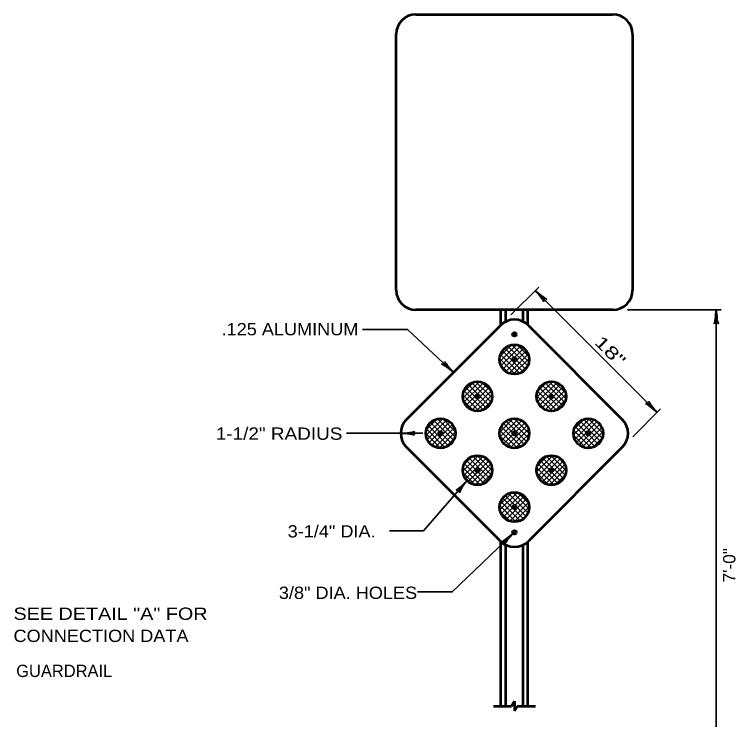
# Model space of a CAD drawing. Extents: x -54 to 626, y -41 to 399.
# Drawn here: x 179.4 to 325.9, y 49.1 to 192.4 of the extents above; entities that cross this region are included whole.
import ezdxf

# ---------------------------------------------------------------- set-up
doc = ezdxf.new("R2010")
doc.units = 0
doc.header["$LTSCALE"] = 0.9
doc.layers.add('1', color=7, linetype='Continuous', lineweight=35)

msp = doc.modelspace()

# ---------------------------------------------------------------- hatches: boundary and pattern name
at = {"layer": '1'}
for points in [[(281.3723, 127.3772, 1), (280.6223, 127.3772, 1)], [(281.3723, 122.2852, 1), (280.6223, 122.2852, 1)], [(273.8723, 114.7853, 1), (273.1223, 114.7853, 1)], [(288.8723, 114.7852, 1), (288.1223, 114.7852, 1)], [(266.3723, 107.2852, 1), (265.6223, 107.2852, 1)], [(281.3723, 107.2852, 1), (280.6223, 107.2852, 1)], [(296.3723, 107.2852, 1), (295.6223, 107.2852, 1)], [(273.8723, 99.7852, 1), (273.1223, 99.7852, 1)], [(288.8723, 99.7853, 1), (288.1223, 99.7853, 1)], [(281.3723, 92.2852, 1), (280.6223, 92.2852, 1)], [(281.3723, 87.1933, 1), (280.6223, 87.1933, 1)]]:
    msp.add_hatch(color=256, dxfattribs=at).paths.add_polyline_path(points)

# ---------------------------------------------------------------- linework, layer by layer
at = {"layer": '1', "lineweight": 53}
for p, q in [((260.9973, 192.3772), (300.9973, 192.3772)), ((256.9973, 136.3772), (256.9973, 188.3772)), ((304.9973, 188.3772), (304.9973, 136.3772)), ((300.9973, 132.3772), (260.9973, 132.3772)), ((278.2473, 129.284), (278.2473, 132.3772)), ((279.2473, 129.974), (279.2473, 132.3772)), ((282.7473, 129.9741), (282.7473, 132.3772)), ((283.7473, 129.284), (283.7473, 132.3772)), ((259.0769, 110.1137), (278.1688, 129.2056)), ((283.8257, 129.2056), (302.9176, 110.1137)), ((278.1688, 85.3649), (259.0769, 104.4568)), ((302.9176, 104.4568), (283.8257, 85.3649)), ((278.2473, 51.8772), (278.2473, 85.2865)), ((283.7473, 51.8772), (283.7473, 85.2865)), ((279.2473, 51.8772), (279.2473, 84.5965)), ((282.7473, 51.8772), (282.7473, 84.5965)), ((280.9973, 52.8772), (280.4199, 51.8772)), ((280.9973, 52.8772), (280.9973, 50.8772)), ((276.7473, 51.8772), (280.4199, 51.8772)), ((280.9973, 50.8772), (281.5746, 51.8772)), ((281.5746, 51.8772), (285.2473, 51.8772))]:
    msp.add_line(p, q, dxfattribs=at)
at = {"layer": '1'}
for p, q in [((280.2901, 131.3268), (285.947, 136.9837)), ((285.2398, 136.2766), (309.9885, 111.5278)), ((303.9973, 132.3772), (322.9973, 132.3772)), ((321.9973, 132.3772), (321.9973, 25.3772)), ((278.0329, 121.8588), (281.426, 125.252)), ((278.0842, 122.9707), (280.3137, 125.2003)), ((278.2742, 121.0395), (282.2457, 125.011)), ((278.6792, 120.3838), (282.896, 124.6007)), ((283.2723, 120.341), (279.0498, 124.5635)), ((283.6929, 120.981), (279.6937, 124.9803)), ((283.9497, 121.7848), (280.4976, 125.2371)), ((283.9344, 122.8609), (281.5714, 125.2239)), ((282.0212, 119.4708), (278.1833, 123.3087)), ((282.7171, 119.8356), (278.5449, 124.0078)), ((279.2254, 119.8694), (283.4107, 124.0547)), ((279.912, 119.4953), (283.7867, 123.37)), ((281.136, 119.2953), (278.0039, 122.4274)), ((280.7758, 119.2984), (283.9817, 122.5044)), ((279.8488, 119.5218), (278.2222, 121.1484)), ((282.0031, 119.4651), (283.8259, 121.2879)), ((270.5224, 114.4162), (273.8635, 117.7574)), ((270.6065, 115.561), (272.7289, 117.6834)), ((270.7516, 113.5848), (274.6968, 117.53)), ((276.2534, 113.619), (272.3268, 117.5457)), ((276.4728, 114.4603), (273.1689, 117.7642)), ((276.38, 115.6137), (274.3293, 117.6645)), ((285.5127, 114.5304), (288.7494, 117.7671)), ((285.6516, 115.7299), (287.5437, 117.6221)), ((285.7145, 113.6716), (289.6074, 117.5644)), ((291.2157, 113.5329), (287.2427, 117.5059)), ((291.4584, 114.3508), (288.0598, 117.7495)), ((291.4139, 115.456), (289.1683, 117.7015)), ((274.6647, 112.0258), (270.7403, 115.9501)), ((275.3357, 112.4154), (271.1322, 116.6188)), ((271.1486, 112.9212), (275.3576, 117.1301)), ((275.8627, 112.9491), (271.6608, 117.1508)), ((271.688, 112.3998), (275.8818, 116.5938)), ((272.3642, 112.0155), (276.2685, 115.9197)), ((289.5777, 111.9889), (285.7047, 115.8618)), ((290.2617, 112.3656), (286.0777, 116.5495)), ((286.0977, 112.9942), (290.2872, 117.1836)), ((290.8062, 112.8816), (286.5888, 117.0992)), ((286.6195, 112.4552), (290.8292, 116.6649)), ((287.277, 112.0521), (291.235, 116.0101)), ((273.8242, 111.8056), (270.5222, 115.1076)), ((273.215, 111.8055), (276.4773, 115.0679)), ((288.7087, 111.7972), (285.5107, 114.9952)), ((288.1039, 111.8183), (291.469, 115.1834)), ((272.6571, 111.912), (270.6222, 113.9469)), ((274.4033, 111.9333), (276.3522, 113.8821)), ((287.4775, 111.9677), (285.6846, 113.7607)), ((289.2213, 111.8751), (291.3998, 114.0537)), ((305.0387, 106.5781), (310.6957, 112.235)), ((263.0336, 106.855), (266.4303, 110.2516)), ((263.0827, 107.9647), (265.3194, 110.2014)), ((263.2758, 106.0364), (267.249, 110.0097)), ((268.6343, 105.8597), (264.5753, 109.9188)), ((268.9219, 106.6328), (265.3477, 110.2071)), ((268.9718, 107.6435), (266.3576, 110.2578)), ((278.0143, 107.5297), (280.7533, 110.2687)), ((278.0908, 106.5455), (281.732, 110.1868)), ((278.3983, 105.7924), (282.4867, 109.8809)), ((283.8335, 106.3152), (280.031, 110.1177)), ((283.9952, 107.2142), (280.9306, 110.2787)), ((283.7096, 108.5603), (282.2672, 110.0027)), ((293.016, 106.9504), (296.3262, 110.2605)), ((293.1197, 108.1147), (295.1724, 110.1674)), ((293.2379, 106.1117), (297.1675, 110.0412)), ((298.8372, 106.3285), (295.0437, 110.1221)), ((298.9957, 107.2308), (295.9468, 110.2796)), ((298.6896, 108.5975), (297.3038, 109.9832)), ((267.6095, 104.7632), (263.4737, 108.8991)), ((263.6814, 105.3814), (267.8986, 109.5987)), ((268.1905, 105.243), (263.9578, 109.4756)), ((264.2279, 104.8673), (268.4126, 109.052)), ((282.3508, 104.6158), (278.3248, 108.6418)), ((282.9819, 105.0454), (278.7538, 109.2735)), ((278.8579, 105.1913), (283.0908, 109.4243)), ((283.479, 105.609), (279.3218, 109.7662)), ((279.4506, 104.7234), (283.5617, 108.8344)), ((297.3623, 104.6214), (293.3311, 108.6527)), ((293.6319, 105.4449), (297.8345, 109.6476)), ((297.9909, 105.0535), (293.7613, 109.2831)), ((294.1655, 104.9179), (298.3646, 109.117)), ((298.4856, 105.6195), (294.3317, 109.7732)), ((294.8357, 104.5274), (298.7575, 108.4492)), ((257.9053, 107.2852), (246.9053, 107.2852)), ((257.9053, 107.2852), (262.3932, 107.287)), ((265.9607, 104.2908), (263.0037, 107.2477)), ((266.8848, 104.4273), (263.135, 108.1771)), ((264.9152, 104.4939), (268.7879, 108.3667)), ((265.7798, 104.2979), (268.982, 107.5001)), ((281.5605, 104.3455), (278.0547, 107.8513)), ((280.1909, 104.403), (283.8837, 108.0959)), ((281.1441, 104.2956), (283.9931, 107.1446)), ((296.5751, 104.348), (293.0581, 107.865)), ((295.6786, 104.3097), (298.9746, 107.6057)), ((264.4924, 104.6983), (263.3982, 105.7926)), ((267.0098, 104.4672), (268.8241, 106.2815)), ((280.517, 104.3283), (278.0434, 106.8019)), ((282.8016, 104.8924), (283.3848, 105.4757)), ((295.5363, 104.3261), (293.0396, 106.8229)), ((296.8438, 104.4142), (298.8678, 106.4382)), ((270.51, 99.5965), (273.686, 102.7726)), ((270.6972, 98.7231), (274.5577, 102.5836)), ((270.6981, 100.8452), (272.4374, 102.5847)), ((276.3313, 98.8075), (272.5238, 102.6151)), ((276.4948, 99.7047), (273.4213, 102.7782)), ((285.517, 99.4455), (288.8317, 102.7602)), ((285.6178, 100.6069), (287.6816, 102.6707)), ((285.74, 98.6078), (289.6718, 102.5397)), ((291.3174, 98.7649), (287.4819, 102.6004)), ((291.4933, 99.6497), (288.3677, 102.7752)), ((291.2594, 100.9442), (289.659, 102.5446)), ((274.8442, 97.1126), (270.8212, 101.1357)), ((271.0696, 98.0348), (275.2482, 102.2133)), ((275.4767, 97.5408), (271.2495, 101.7681)), ((271.5814, 97.486), (275.7999, 101.7045)), ((275.9753, 98.1029), (271.8162, 102.2621)), ((276.2211, 101.0392), (274.7513, 102.5088)), ((289.8061, 97.0942), (285.8007, 101.0997)), ((286.1344, 97.9416), (290.3379, 102.1451)), ((290.447, 97.514), (286.2246, 101.7363)), ((286.6688, 97.4153), (290.8672, 101.6137)), ((290.9537, 98.068), (286.7832, 102.2385)), ((274.0522, 96.8441), (270.5528, 100.3435)), ((272.2286, 97.0724), (276.212, 101.0559)), ((273.0422, 96.8254), (276.4597, 100.243)), ((289.0037, 96.836), (285.5416, 100.2981)), ((287.3399, 97.0258), (291.2592, 100.945)), ((288.184, 96.8092), (291.475, 100.1002)), ((273.0059, 96.8297), (270.5456, 99.29)), ((274.1357, 96.8582), (276.4264, 99.149)), ((287.9417, 96.8373), (285.5586, 99.2205)), ((289.3526, 96.9171), (291.3655, 98.93)), ((278.0358, 92.7443), (280.5364, 95.2448)), ((278.0607, 91.7084), (281.5752, 95.223)), ((283.9696, 91.9359), (280.6429, 95.2626)), ((278.3338, 90.9209), (282.363, 94.9502)), ((282.8193, 89.9042), (278.6201, 94.1034)), ((278.765, 90.2914), (282.995, 94.5214)), ((283.3501, 90.4341), (279.1448, 94.6393)), ((279.3299, 89.7957), (283.4863, 93.9522)), ((283.745, 91.0998), (279.8063, 95.0385)), ((283.8875, 93.0787), (281.7935, 95.1726)), ((281.3007, 89.3015), (278.0196, 92.5826)), ((282.1461, 89.5168), (278.2324, 93.4304)), ((280.038, 89.4432), (283.8347, 93.2399)), ((280.9459, 89.2903), (283.9935, 92.338)), ((280.1198, 89.4217), (278.1359, 91.4056)), ((282.3143, 89.5981), (283.6897, 90.9735))]:
    msp.add_line(p, q, dxfattribs=at)
for points in [[(268.6229, 119.6597), (259.2493, 128.3586), (250.1317, 128.3586)], [(271.3759, 97.6639), (262.5505, 87.4735), (255.6337, 87.4735)], [(280.7321, 86.9282), (268.3668, 75.0507), (261.2928, 75.0507)]]:
    msp.add_lwpolyline(points, dxfattribs=at)
at = {"layer": '1', "lineweight": 53}
for centre, radius in [((280.9973, 127.3772), 0.375), ((280.9973, 122.2852), 3), ((280.9973, 122.2852), 0.375), ((273.4973, 114.7853), 3), ((288.4973, 114.7852), 3), ((273.4973, 114.7853), 0.375), ((288.4973, 114.7852), 0.375), ((265.9973, 107.2852), 3), ((280.9973, 107.2852), 3), ((295.9973, 107.2852), 3), ((265.9973, 107.2852), 0.375), ((280.9973, 107.2852), 0.375), ((295.9973, 107.2852), 0.375), ((273.4973, 99.7852), 3), ((288.4973, 99.7853), 3), ((273.4973, 99.7852), 0.375), ((288.4973, 99.7853), 0.375), ((280.9973, 92.2852), 3), ((280.9973, 92.2852), 0.375), ((280.9973, 87.1933), 0.375)]:
    msp.add_circle(centre, radius, dxfattribs=at)
for centre, start, end in [((260.9973, 188.3772), 90, 180), ((300.9973, 188.3772), 0, 90), ((260.9973, 136.3772), 180, 270), ((300.9973, 136.3772), 270, 0), ((280.9973, 126.3772), 45.00033, 135), ((261.9054, 107.2852), 135, 225), ((300.0892, 107.2853), 315, 44.99948), ((280.9973, 88.1934), 225, 315)]:
    msp.add_arc(centre, 4, start, end, dxfattribs=at)
at = {"layer": '1', "lineweight": 40}
for centre, major_axis, ratio, start_param, end_param in [((285.8825, 135.3346), (-1.1178, 1.3662), 0.07063, 3.14071475, 5.41810995), ((285.8825, 135.3346), (-1.1178, 1.3662), 0.07063, 3.14071475, 5.41810995), ((286.2068, 135.7004), (-1.3731, 1.1523), 0.122415, 0.89635335, 3.14159265), ((286.2068, 135.7004), (-1.3731, 1.1523), 0.122415, 0.89635335, 3.14159265), ((321.7856, 131.2567), (0.1757, 1.7565), 0.07063, 3.14071475, 5.41810995), ((322.2735, 131.286), (-0.1562, 1.7857), 0.122415, 0.89635335, 3.14159265), ((267.9455, 120.577), (-1.168, 1.3235), 0.07063, 6.28230741, 8.55970261), ((267.9455, 120.577), (-1.168, 1.3235), 0.07063, 6.28230741, 8.55970261), ((267.6351, 120.1994), (1.4151, -1.1002), 0.122415, 0.89635335, 3.14159265), ((267.6351, 120.1994), (1.4151, -1.1002), 0.122415, 0.89635335, 3.14159265), ((309.0215, 112.1041), (1.3731, -1.1523), 0.122415, 0.89635335, 3.14159265), ((309.0215, 112.1041), (1.3731, -1.1523), 0.122415, 0.89635335, 3.14159265), ((309.3458, 112.4698), (1.1178, -1.3662), 0.07063, 3.14071475, 5.41810995), ((309.3458, 112.4698), (1.1178, -1.3662), 0.07063, 3.14071475, 5.41810995), ((259.0259, 107.0741), (-1.7565, 0.175), 0.07063, 3.14071475, 5.41810995), ((258.9964, 107.562), (-1.7856, -0.1568), 0.122415, 0.89635335, 3.14159265), ((270.4824, 96.9554), (-1.2827, -1.2127), 0.07063, 6.28230741, 8.55970261), ((270.4824, 96.9554), (-1.2827, -1.2127), 0.07063, 6.28230741, 8.55970261), ((270.8704, 96.6582), (1.051, 1.4521), 0.122415, 0.89635335, 3.14159265), ((270.8704, 96.6582), (1.051, 1.4521), 0.122415, 0.89635335, 3.14159265), ((279.7774, 86.3046), (-1.3884, -1.0901), 0.07063, 6.28230741, 8.55970261), ((279.7774, 86.3046), (-1.3884, -1.0901), 0.07063, 6.28230741, 8.55970261), ((280.1365, 85.973), (1.1797, 1.3496), 0.122415, 0.89635335, 3.14159265), ((280.1365, 85.973), (1.1797, 1.3496), 0.122415, 0.89635335, 3.14159265)]:
    msp.add_ellipse(centre, major_axis=major_axis, ratio=ratio, start_param=start_param, end_param=end_param, dxfattribs=at)

# ---------------------------------------------------------------- texts
at = {"layer": '1'}
for s, width, p in [('.125 ALUMINUM', 1.1, (221.5157, 127.1863)), ('1-1/2" RADIUS', 1.15, (220.3367, 105.9643)), ('3-1/4" DIA.', 1.1, (234.9374, 86.1187)), ('3/8" DIA. HOLES', 1.1, (233.1542, 73.6316)), ('SEE DETAIL "A" FOR', 1.2, (179.255, 69.3844)), ('CONNECTION DATA', 1.1, (179.255, 64.8844))]:
    msp.add_text(s, height=2.5, dxfattribs=dict(at, width=width)).set_placement(p)
for s, rotation, width, p in [('18"', 315, 1.45, (297.0524, 125.6204)), ('7\'-0"', 90, 1.05, (325.8857, 76.9763))]:
    msp.add_text(s, height=2.5, rotation=rotation, dxfattribs=dict(at, width=width)).set_placement(p)
msp.add_text('GUARDRAIL', height=2.5, dxfattribs=at).set_placement((179.8025, 57.7682))

doc.saveas('drawing.dxf')
